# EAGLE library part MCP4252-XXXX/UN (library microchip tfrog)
MCP4252 7/8-Bit Dual SPI Digital Rheostat with Volatile Memory Doc: http://www.microchip.com/wwwproducts/Devices.aspx?dDocName=en531890 Ref Used: MCP4252-502E/UN (8 bits, 5K ohms)
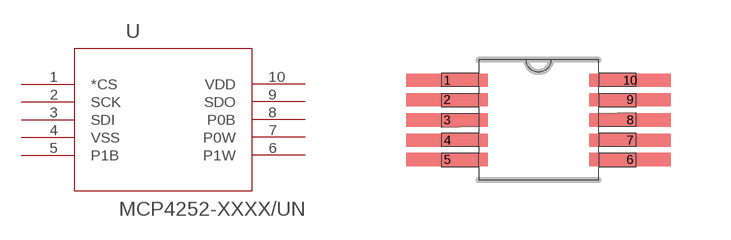
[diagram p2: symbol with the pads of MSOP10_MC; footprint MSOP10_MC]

Designator prefix -

## MCP4252-XXXX/UN  [MSOP10_MC]
1  *CS  pas
2  SCK  pas
3  SDI  pas
4  VSS  pas
5  P1B  pas
6  P1W  pas
7  P0W  pas
8  P0B  pas
9  SDO  pas
10  VDD  pas

## Footprint MSOP10_MC (pad centres in mm)
MSOP10 with long pads (0.08inch instead of 0.06)
smd 2.032 x 0.33: 1 -2.286,0.991; 2 -2.286,0.508; 3 -2.286,0; 4 -2.286,-0.508; 5 -2.286,-0.991; 6 2.286,-0.991; 7 2.286,-0.508; 8 2.286,0; 9 2.286,0.508; 10 2.286,0.991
